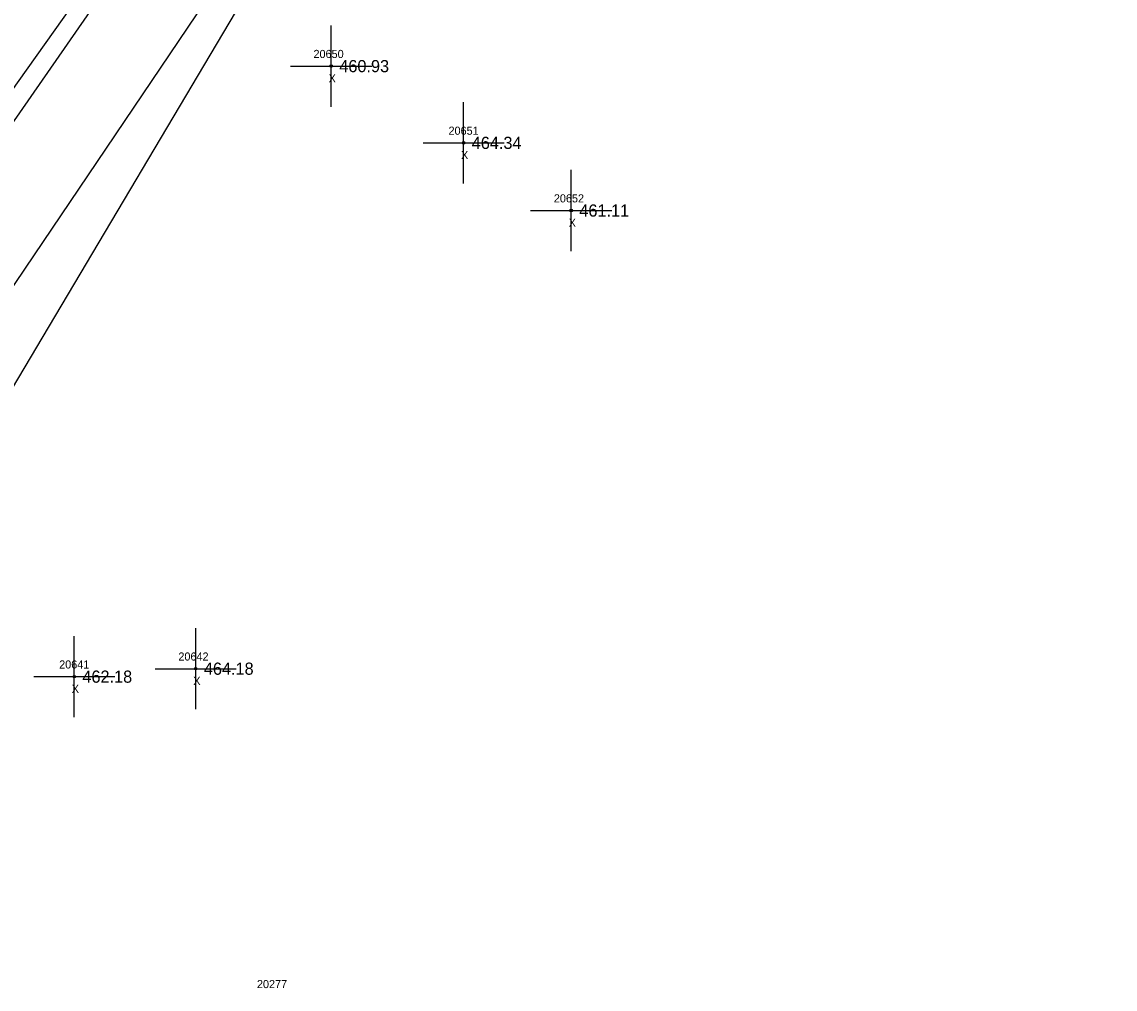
# Model space of a CAD drawing. Extents: x 1785066 to 1786589, y 770293 to 771312.
# Drawn here: x 1785893.3 to 1786028, y 770938.9 to 771058.2 of the extents above; entities that cross this region are included whole.
import ezdxf

# ---------------------------------------------------------------- set-up
doc = ezdxf.new("R2010")
doc.units = 0
for name, color, linetype in [('RD_DTM_BkLn_txCode', 7, 'Continuous'), ('RD_EX_H2O', 7, 'Continuous'), ('RD_EX_Misc', 7, 'Continuous'), ('RD_EX_Misc_txCode', 7, 'Continuous'), ('RD_EX_TX_Misc_ELEV', 7, 'Continuous'), ('RD_SMD_Locator', 7, 'Continuous')]:
    doc.layers.add(name, color=color, linetype=linetype)

msp = doc.modelspace()

# ---------------------------------------------------------------- linework, layer by layer
at = {"layer": 'RD_EX_H2O'}
for points in [[(1785796.94, 770894.21), (1785817.52, 770934.08), (1785841.28, 770978.27), (1785905.84, 771069.13), (1785934.06, 771107.4), (1785932.74, 771138.87), (1785957.1, 771183.16), (1785993.97, 771208.54), (1785990.48, 771236.16), (1786004.55, 771296.27)], [(1785809.1, 770721.92), (1785797.13, 770787.08), (1785799.71, 770830.45), (1785797.84, 770854.32), (1785797.31, 770871.66), (1785799.74, 770882.87), (1785807.79, 770893.6), (1785824.76, 770932.46), (1785830, 770936.66), (1785845.12, 770978.01), (1785907.84, 771068.37), (1785939.25, 771107.77), (1785943.33, 771137.21), (1785960.57, 771178.58), (1785995.85, 771206.75), (1786007.06, 771230.75), (1786010.67, 771288.67)], [(1785820.66, 770730.64), (1785814.87, 770787.58), (1785810.48, 770814.19), (1785812.13, 770827.02), (1785814.82, 770830.33), (1785807.38, 770854.48), (1785804.49, 770870.81), (1785818.14, 770890.97), (1785834.56, 770929.05), (1785857.87, 770974.7), (1785917.08, 771062.46), (1785943.86, 771096.04), (1785952.84, 771134.11), (1785966.16, 771175.54), (1786004.33, 771202.23), (1786012.95, 771230.11), (1786017.56, 771287.45)], [(1785823.91, 770890.02), (1785840.03, 770925.86), (1785869.79, 770975.48), (1785920.39, 771060.62), (1785947.12, 771092.26), (1785958.51, 771131.14), (1785974.06, 771169.93), (1786009.64, 771197.71), (1786027.99, 771233.04), (1786021.73, 771286.51)]]:
    msp.add_lwpolyline(points, dxfattribs=at)
at = {"layer": 'RD_EX_Misc'}
for p, q in [((1785931.38, 771047.7), (1785931.38, 771057.7)), ((1785926.38, 771052.7), (1785936.38, 771052.7)), ((1785947.7, 771038.24), (1785947.7, 771048.24)), ((1785942.7, 771043.24), (1785952.7, 771043.24)), ((1785960.96, 771029.9), (1785960.96, 771039.9)), ((1785955.96, 771034.9), (1785965.96, 771034.9)), ((1785914.69, 770973.42), (1785914.69, 770983.42)), ((1785899.72, 770972.44), (1785899.72, 770982.44)), ((1785909.69, 770978.42), (1785919.69, 770978.42)), ((1785894.72, 770977.44), (1785904.72, 770977.44))]:
    msp.add_line(p, q, dxfattribs=at)
at = {"layer": 'RD_SMD_Locator'}
for centre in [(1785931.38, 771052.7), (1785947.7, 771043.24), (1785960.96, 771034.9), (1785914.69, 770978.42), (1785899.72, 770977.44)]:
    msp.add_circle(centre, 0.15, dxfattribs=at)

# ---------------------------------------------------------------- texts
at = {"layer": 'RD_DTM_BkLn_txCode'}
msp.add_text('20277', height=1, dxfattribs=at).set_placement((1785922.23, 770939.04))
at = {"layer": 'RD_EX_Misc_txCode'}
for s, p in [('20650', (1785929.2, 771053.7)), ('X', (1785931.06, 771050.7)), ('20651', (1785945.84, 771044.24)), ('X', (1785947.38, 771041.24)), ('20652', (1785958.82, 771035.9)), ('X', (1785960.65, 771032.9)), ('20641', (1785897.86, 770978.44)), ('20642', (1785912.55, 770979.42)), ('X', (1785914.38, 770976.42)), ('X', (1785899.41, 770975.44))]:
    msp.add_text(s, height=1, dxfattribs=at).set_placement(p)
at = {"layer": 'RD_EX_TX_Misc_ELEV'}
for s, p in [('460.93', (1785932.38, 771051.95)), ('464.34', (1785948.7, 771042.49)), ('461.11', (1785961.96, 771034.15)), ('462.18', (1785900.72, 770976.69)), ('464.18', (1785915.69, 770977.67))]:
    msp.add_text(s, height=1.5, dxfattribs=at).set_placement(p)

doc.saveas('drawing.dxf')
